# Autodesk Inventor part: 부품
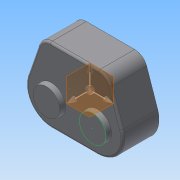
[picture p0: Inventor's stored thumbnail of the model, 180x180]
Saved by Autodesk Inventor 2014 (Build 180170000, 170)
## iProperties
Created: 2014-12
Part Number: 부품
Material: 일반
Document SubType Name: Modeling
Designer: net
Density: 1 g/cm^3
Appearance: 기본값
Author: net
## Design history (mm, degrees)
sketch "스케치1"
  geometry: L1 (-47, 36)-(47, 36); L2 (47, 36)-(66.565, -20.803); L3 (-47, 36)-(-66.565, -20.803); L4 (-32.527, -68.527)-(32.527, -68.527); L5 (0, 0)-(-32.527, -32.527); L6 (0, 0)-(0, -68.527); A1 r 36 centre (-32.527, -32.527) between (-66.565, -20.803) and (-32.527, -68.527); A2 r 36 centre (32.527, -32.527) between (32.527, -68.527) and (66.565, -20.803); A3 r 46 centre (0, 0) between (-32.527, -32.527) and (32.527, -32.527); 2 further points
  constraints: 12 end point, 6 point on circle, 3 centre point, 3 tangent, 2 midpoint, 1 coincident, 1 equal radius, 1 horizontal, 1 horizontal alignment, 1 parallel, 1 perpendicular, 1 vertical alignment
  dimensions: "d16" = 46 radius of A3; "d17" = 45 deg angle of L6 L5; "d18" = 36 radius of A1; "d19" = 94 distance of L1.start L1.end; "d20" = 36 distance from line of point (0, 0) L1
extrude "돌출1" new body sketch "스케치1" distance "d21" = 51; taper "d22" = 0 deg
fillet "모깎기1" dims "d23" = 18
fillet "모깎기2" dims "d24" = 3
sketch "스케치2"
  geometry: C1 r 20 at (-32.527, -32.527); C2 r 20 at (32.527, -32.527); A1 r 33 centre (-32.527, -32.527) between (-63.728, -21.78) and (-32.527, -65.527) reference; A2 r 33 centre (32.527, -32.527) between (32.527, -65.527) and (63.728, -21.78) reference; 1 further point
  constraints: 2 centre point, 2 coincident, 1 equal radius
  dimensions: "d25" = 40 diameter of C1
extrude "돌출2" join sketch "스케치2" distance "d26" = 7; taper "d27" = -10 deg
feature "쉘1" dims "d40" = 5
sketch "스케치5"
  geometry: C1 r 15.805 at (66.689, -63.527) reference; C2 r 15.805 at (1.635, -63.527) reference; C3 r 24 at (1.635, -63.527); C4 r 24 at (66.689, -63.527); 1 further point
  constraints: 2 centre point, 2 coincident, 1 equal radius
  dimensions: "d61" = 48 diameter of C3
extrude "돌출3" join sketch "스케치5" distance "d62" = 11; taper "d63" = 0 deg
node "작업 평면1"
sketch "스케치6"
  geometry: C1 r 18.766 at (0, 0) reference; 1 further point
hole "구멍3" diameter "d54" = 30; stored, may be unused: countersink angle "d58" = 90 deg, drill point angle "d60" = 118 deg; dims "d50" = 10, "d51" = 10, "d55" = 6, "d56" = 30, "d57" = 7, "d59" = 7
hole "구멍2" diameter "d43" = 15.5; stored, may be unused: countersink angle "d47" = 90 deg, drill point angle "d49" = 118 deg; dims "d44" = 6, "d45" = 30, "d46" = 7, "d48" = 10, "d52" = 10, "d53" = 10
sketch "스케치4"
  geometry: L1 (34.162, 36)-(-34.162, 36) reference; L2 (-51.181, 23.862)-(-66.565, -20.803) reference; L3 (-32.527, -68.527)-(32.527, -68.527) reference; L4 (66.565, -20.803)-(51.181, 23.862) reference; L5 (-34.162, 30)-(34.162, 30); L6 (45.508, 21.908)-(60.892, -22.757); L7 (32.527, -62.527)-(-32.527, -62.527); L8 (-60.892, -22.757)-(-45.508, 21.908); A1 r 18 centre (34.162, 18) between (51.181, 23.862) and (34.162, 36) reference; A2 r 18 centre (-34.162, 18) between (-34.162, 36) and (-51.181, 23.862) reference; A3 r 36 centre (-32.527, -32.527) between (-66.565, -20.803) and (-32.527, -68.527) reference; A4 r 36 centre (32.527, -32.527) between (32.527, -68.527) and (66.565, -20.803) reference; A5 r 12 centre (34.162, 18) between (45.508, 21.908) and (34.162, 30); A6 r 30 centre (32.527, -32.527) between (32.527, -62.527) and (60.892, -22.757); A7 r 30 centre (-32.527, -32.527) between (-60.892, -22.757) and (-32.527, -62.527); A8 r 12 centre (-34.162, 18) between (-34.162, 30) and (-45.508, 21.908); 1 further point
  constraints: 8 end point, 8 point on circle, 4 centre point, 7 other
  dimensions: "d39" = 6 distance between parallel lines of L1 L5
sketch "스케치3"
  geometry: 1 further point
node "솔리드1"
